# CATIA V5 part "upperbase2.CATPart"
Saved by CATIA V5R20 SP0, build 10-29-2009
Part number: ub2.1
Bounding box of the stored display mesh (mm): x -5 to 355, y 0 to 905, z -596 to 5
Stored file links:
  C:\Users\HP\Downloads\Catia Project\Catia Project\upperbase2.CATPart
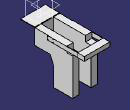
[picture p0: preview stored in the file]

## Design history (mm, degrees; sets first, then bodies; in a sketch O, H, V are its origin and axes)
Body1 (main body)
  Sketch1 on xy-plane, origin (0, 0, 0), H (1, 0, 0), V (0, 1, 0)
    line L1 (0, 0) -> (350, 0)
    line L2 (350, 0) -> (350, 200)
    line L3 (350, 200) -> (0, 200)
    line L4 (0, 200) -> (0, 0)
    length L1 = 350
    length L4 = 200
    horizontal: L1 H, L3 H
    vertical: L2 V, L4 V
  Pad1: profile Sketch1, direction (0, 0, 1), length 5
  Sketch2 on face of Pad1 from Sketch1.L3, origin (0, 200, 0), H (-1, 0, 0), V (0, 0, 1)
    line L1 (-350, 5) -> (0, 5)
    line L2 (0, 5) -> (0, -217)
    line L3 (0, -217) -> (-350, -217)
    line L4 (-350, -217) -> (-350, 5)
    reference projected line E1 (-350, 5) -> (0, 5) from edge [face of Pad1 from Sketch1.L3 | end face of Pad1]
    reference projected line E2 (0, 0) -> (0, 5) from edge [face of Pad1 from Sketch1.L4 | face of Pad1 from Sketch1.L3]
    reference projected line E3 (-350, 0) -> (-350, 5) from edge [face of Pad1 from Sketch1.L3 | face of Pad1 from Sketch1.L2]
    length L4 = 222
    horizontal: L1 H, L3 H
    vertical: L2 V, L4 V
    coincidence: L1 E1, E2 L2, L4 E3
  Pad2: profile Sketch2, direction (0, 1, 0), length 5
  Fillet1: radius 5, on edge [face of Pad2 | end face of Pad2]
  Sketch3 on end face of Pad2, origin (0, 205, 0), H (-1, 0, 0), V (0, 0, 1)
    line L1 (-350, 0) -> (-261, 0)
    line L2 (-261, 0) -> (-261, -217)
    line L3 (-261, -217) -> (-350, -217)
    line L4 (-350, -217) -> (-350, 0)
    reference projected line E1 (-350, 5) -> (-350, -217) from edge [face of Pad2 | end face of Pad2]
    reference projected line E2 (-350, -217) -> (0, -217) from edge [face of Pad2 from Sketch2.L3 | end face of Pad2]
    reference projected line E3 (0, 0) -> (-350, 0) from edge [face of Fillet1 | end face of Pad2]
    line L5 (-89, 0) -> (0, 0)
    line L6 (0, 0) -> (0, -217)
    line L7 (0, -217) -> (-89, -217)
    line L8 (-89, -217) -> (-89, 0)
    reference projected line E4 (0, -217) -> (0, 5) from edge [face of Pad2 | end face of Pad2]
    reference projected line E5 (0, 0) -> (-350, 0) from edge [face of Fillet1 | end face of Pad2]
    reference projected line E6 (-350, -217) -> (0, -217) from edge [face of Pad2 from Sketch2.L3 | end face of Pad2]
    length L1 = 89
    length L5 = 89
    horizontal: L1 H, L3 H, L5 H, L7 H
    vertical: L2 V, L4 V, L6 V, L8 V
    coincidence: L4 E1, E2 L3, L1 E3, L6 E4, L5 E5, L7 E6
  Pad3: profile Sketch3, direction (0, 1, 0), length 530
  Sketch4 on face of Pad3, origin (0, 0, -217), H (1, 0, 0), V (0, -1, 0)
    line L1 (0, -467.96) -> (89, -467.96)
    line L2 (89, -467.96) -> (89, -735)
    line L3 (89, -735) -> (0, -735)
    line L4 (0, -735) -> (0, -467.96)
    reference projected line E1 (0, -735) -> (89, -735) from edge [face of Pad3 | end face of Pad3]
    reference projected line E3 (89, -205) -> (89, -735) from edge [face of Pad3 | face of Pad3 from Sketch3.L8]
    reference projected line E4 (0, -200) -> (0, -205) from edge [face of Pad3 | face of Pad3]
    line L5 (261, -467.96) -> (350, -467.96)
    line L6 (350, -467.96) -> (350, -735)
    line L7 (350, -735) -> (261, -735)
    line L8 (261, -735) -> (261, -467.96)
    reference projected line E5 (0, -735) -> (89, -735) from edge [face of Pad3 | end face of Pad3]
    reference projected line E7 (350, -200) -> (350, -205) from edge [face of Pad3 | face of Pad3]
    reference projected line E8 (261, -205) -> (261, -735) from edge [face of Pad3 from Sketch3.L2 | face of Pad3]
    length L4 = 267.04
    length L6 = 267.04
    horizontal: L1 H, L3 H, L5 H, L7 H
    vertical: L2 V, L4 V, L6 V, L8 V
    coincidence: L3 E1, L2 E3, L4 E4, E5 L7, L6 E7, L8 E8
  Pad4: profile Sketch4, direction (0, 0, -1), length 379
  Sketch5 on face of Pad4, origin (0, 0, 0), H (0, -1, 0), V (0, 0, 1)
    line L1 (-467.96, -217) -> (-467.96, -336.08)
    line L2 (-467.96, -217) -> (-419.24, -217)
    reference projected line E1 (-467.96, -217) -> (-467.96, -596) from edge [face of Pad4 | face of Pad4 from Sketch4.L1]
    reference projected line E2 (-200, -217) -> (-205, -217) from edge [face of Pad4 | face of Pad3]
    line L3 (-467.96, -336.08) -> (-419.24, -217)
    length L1 = 119.08
    length L2 = 48.72
    vertical: L1 V
    horizontal: L2 H
    coincidence: L1 E1, L2 E2
  Pad5: profile Sketch5, direction (1, 0, 0), length 89
  Sketch6 on face of Pad4, origin (350, 0, 0), H (0, 1, 0), V (0, 0, 1)
    line L1 (467.96, -217) -> (467.96, -336.08)
    line L2 (467.96, -217) -> (419.24, -217)
    reference projected line E1 (200, -217) -> (205, -217) from edge [face of Pad3 | face of Pad4]
    reference projected line E2 (467.96, -217) -> (467.96, -596) from edge [face of Pad4 from Sketch4.L5 | face of Pad4]
    line L3 (419.24, -217) -> (467.96, -336.08)
    length L1 = 119.08
    length L2 = 48.72
    vertical: L1 V
    horizontal: L2 H
    coincidence: L2 E1, L1 E2
  Pad6: profile Sketch6, direction (-1, 0, 0), length 89
  Sketch7 on face of Pad6, origin (350, 0, 0), H (0, 1, 0), V (0, 0, 1)
    line L1 (655, 0) -> (735, 0)
    line L2 (735, 0) -> (735, -80)
    line L3 (735, -80) -> (655, -80)
    line L4 (655, -80) -> (655, 0)
    reference projected line E1 (205, 0) -> (735, 0) from edge [face of Pad6 | face of Pad3 from Sketch3.L1]
    reference projected line E2 (735, 0) -> (735, -217) from edge [face of Pad6 | face of Pad4]
    length L2 = 80
    length L1 = 80
    horizontal: L1 H, L3 H
    vertical: L2 V, L4 V
    coincidence: L1 E1, L2 E2
  Pocket1: profile Sketch7, direction (-1, 0, 0), through (limit type 3)
  Sketch8 on face of Pad6, origin (350, 0, 0), H (0, 1, 0), V (0, 0, 1)
    line L1 (379.64, 0) -> (655, 0)
    line L2 (655, 0) -> (655, -56.93)
    line L3 (655, -56.93) -> (379.64, -56.93)
    line L4 (379.64, -56.93) -> (379.64, 0)
    reference projected line E1 (655, 0) -> (655, -80) from edge [face of Pad6 | face of Pocket1 from Sketch7.L4]
    reference projected line E2 (205, 0) -> (735, 0) from edge [face of Pad6 | face of Pad3 from Sketch3.L1]
    length L4 = 56.93
    length L1 = 275.36
    horizontal: L1 H, L3 H
    vertical: L4 V
    coincidence: L2 E1, L1 E2
  Pad7: profile Sketch8, direction (1, 0, 0), length 5
  Sketch9 on face of Pad7, origin (0, 655, 0), H (-1, 0, 0), V (0, 0, 1)
    line L1 (-355, 0) -> (-350, 0)
    line L2 (-350, 0) -> (-350, -56.93)
    line L3 (-350, -56.93) -> (-355, -56.93)
    line L4 (-355, -56.93) -> (-355, 0)
    reference projected line E1 (-355, -56.93) -> (-355, 0) from edge [face of Pad7 from Sketch8.L2 | end face of Pad7]
    reference projected line E2 (-355, 0) -> (-261, 0) from edge [face of Pad7 | face of Pad7]
    reference projected line E3 (-350, -56.93) -> (-355, -56.93) from edge [face of Pad7 | face of Pad7 from Sketch8.L3]
    length L1 = 5
    horizontal: L1 H, L3 H
    vertical: L2 V, L4 V
    coincidence: L4 E1, L1 E2, L3 E3
  Pad8: profile Sketch9, direction (0, -1, 0), length 250
  Pad9: profile Sketch9, direction (0, 1, 0), length 250
  Plane1: type Offset, RefPlane yz-plane, Offset 175
  Mirror1: of Pad7, about Plane1
  Mirror2: of Pad8, about Plane1
  Mirror3: of Pad9, Sketch9, about Plane1
  Sketch10 on face of Pad9, origin (355, 0, 0), H (0, 1, 0), V (0, 0, 1)
    circle A1 centre (463.96, -11.16) radius 4
    point P1 (463.96, -11.16)
    reference projected line E1 (655, -56.93) -> (655, -80) from edge [face of Pad6 | face of Pad8]
    reference projected line E2 (655, 0) -> (379.64, 0) from edge [face of Pad9 | face of Pad9]
    circle A2 centre (463.96, -46.61) radius 4
    point P2 (463.96, -46.61)
    circle A3 centre (390.47, -11.16) radius 4
    point P3 (390.47, -11.16)
    circle A4 centre (390.47, -46.61) radius 4
    radius A1 = 4
    distance P1 E1 = 191.04
    distance P1 E2 = 11.16
    radius A2 = 4
    distance P1 P2 = 35.45
    radius A3 = 4
    distance P3 P1 = 73.49
    radius A4 = 4
  Pocket2: profile Sketch10, direction (-1, 0, 0), length 30
  Mirror4: of Pocket2, about Plane1
  Sketch11 on face of Pad9 from Sketch9.L2, origin (350, 0, 0), H (0, -1, 0), V (0, 0, 1)
    line L1 (-905, 0) -> (-811.1299, 0)
    line L2 (-811.1299, 0) -> (-811.1299, -56.93)
    line L3 (-811.1299, -56.93) -> (-905, -56.93)
    line L4 (-905, -56.93) -> (-905, 0)
    reference projected line E1 (-655, 0) -> (-379.64, 0) from edge [face of Mirror3 | face of Mirror3]
    reference projected line E2 (-905, 0) -> (-905, -56.93) from edge [face of Mirror3 | face of Mirror3]
    reference projected line E3 (-379.64, -56.93) -> (-655, -56.93) from edge [face of Mirror3 | face of Mirror3]
    horizontal: L1 H, L3 H
    vertical: L2 V, L4 V
    coincidence: L1 E1, L4 E2, L3 E3
  Pad10: profile Sketch11, direction (-1, 0, 0), up to the existing solid (limit type 2)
